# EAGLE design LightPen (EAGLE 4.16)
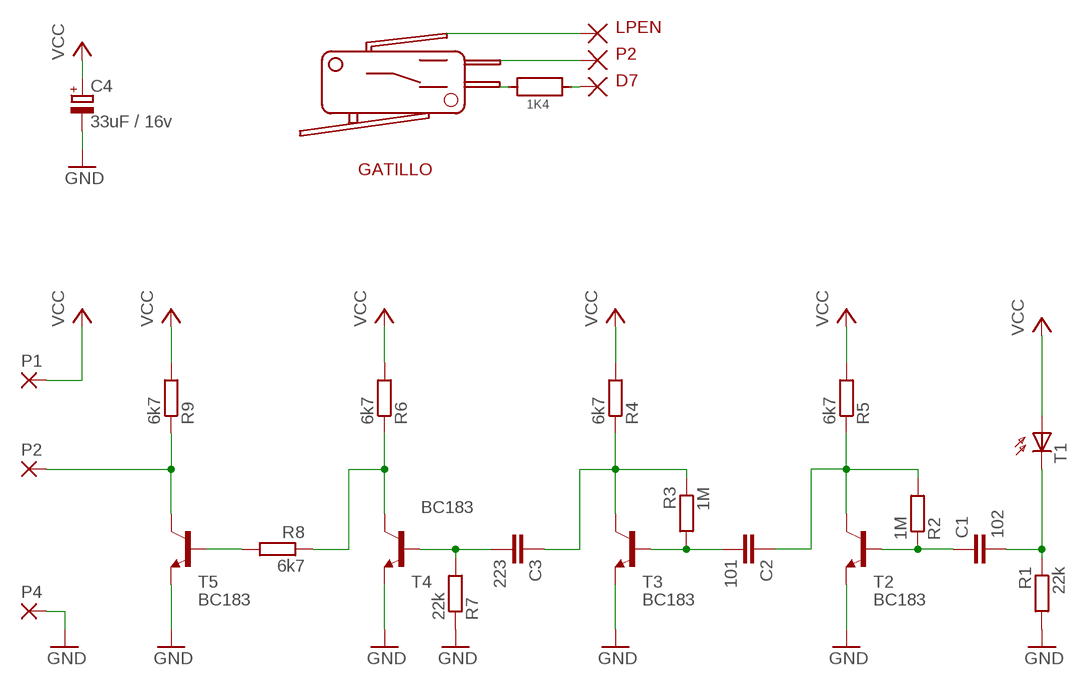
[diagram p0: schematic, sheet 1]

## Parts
C1  102  C-EU025-025X050  [C025-025X050]
C2  101  C-EU050-025X075  [C050-025X075]
C3  223  C-EU050-025X075  [C050-025X075]
C4  33uF / 16v  CPOL-EUE2.5-6  [E2,5-6]
P1  SMD2  [SMD1,27-2,54]
P2  SMD2  [SMD1,27-2,54]
P4  SMD2  [SMD1,27-2,54]
R1  22k  R-EU_0207/10  [0207/10]
R2  1M  R-EU_0207/10  [0207/10]
R3  1M  R-EU_0207/10  [0207/10]
R4  6k7  R-EU_0207/10  [0207/10]
R5  6k7  R-EU_0207/10  [0207/10]
R6  6k7  R-EU_0207/10  [0207/10]
R7  22k  R-EU_0207/10  [0207/10]
R8  6k7  R-EU_0207/10  [0207/10]
R9  6k7  R-EU_0207/10  [0207/10]
T1  SFH206  [SFH206]
T2  BC183  -NPN-TO92  [TO92]
T3  BC183  -NPN-TO92  [TO92]
T4  BC183  -NPN-TO92  [TO92]
T5  BC183  -NPN-TO92  [TO92]

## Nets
GND: C4.- P4.1(P) R1.2 R7.1 T2.1(E) T3.1(E) T4.1(E) T5.1(E)
N$1: P2.1(P) R9.1 T5.3(C)
N$2: R8.2 T5.2(B)
N$3: C1.2 R1.1 T1.K(C)
N$4: C1.1 R2.1 T2.2(B)
N$5: C2.1 R2.2 R5.1 T2.3(C)
N$6: C2.2 R3.2 T3.2(B)
N$7: C3.1 R3.1 R4.1 T3.3(C)
N$8: C3.2 R7.2 T4.2(B)
N$9: R6.1 R8.1 T4.3(C)
VCC: C4.+ P1.1(P) R4.2 R5.2 R6.2 R9.2 T1.A

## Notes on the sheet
- LPEN
- P2
- D7
- 1K4
- GATILLO

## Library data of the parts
C1-C3 = rcl:C-EU: CAPACITOR, European symbol
C4 = rcl:CPOL-EU: POLARIZED CAPACITOR, European symbol
P1 P2 P4 = wirepad:SMD2: SMD PAD
R1-R9 = rcl:R-EU_: RESISTOR, European symbol
T1 = opto-trans-siemens:SFH206: PHOTO DIODE
T2-T5 = transistor:*-NPN-: NPN Transistror

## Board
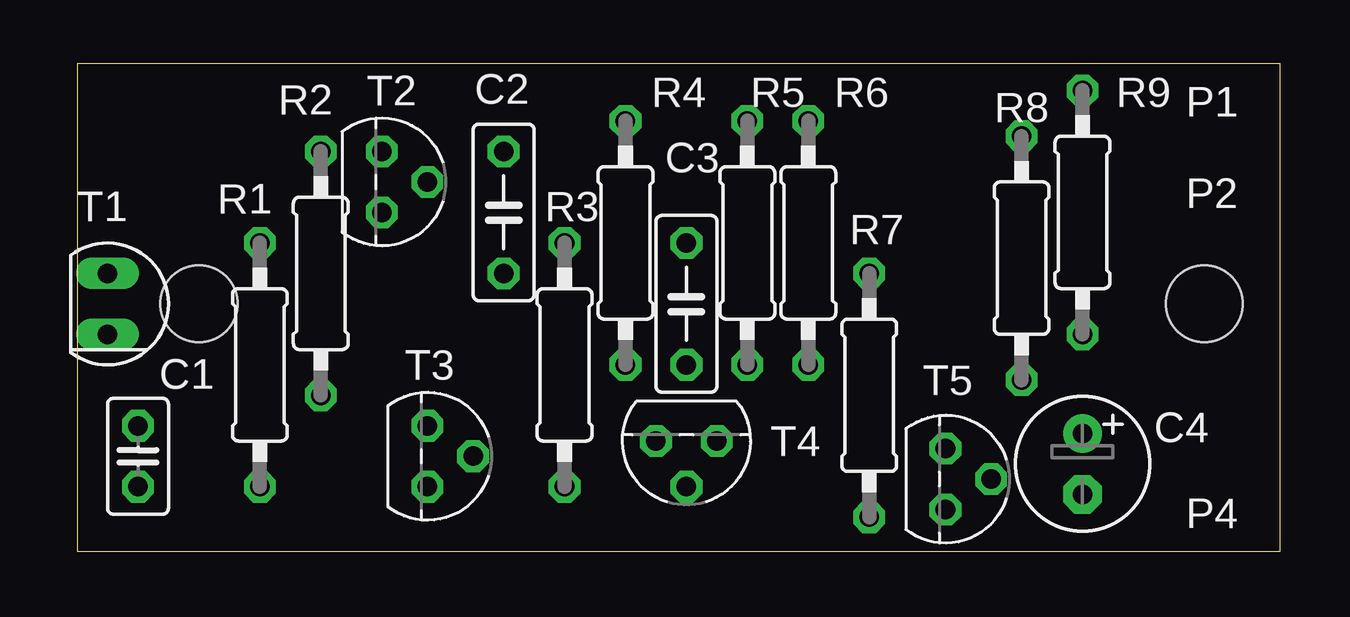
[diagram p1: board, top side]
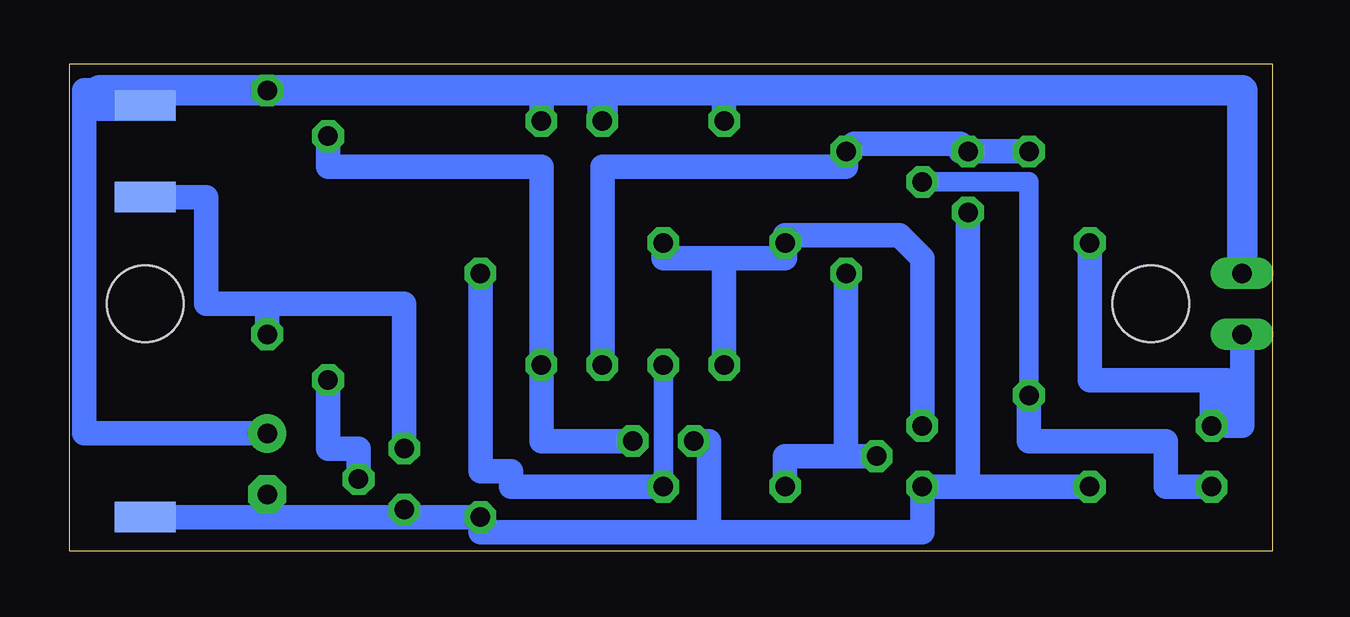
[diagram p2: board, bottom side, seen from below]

Size 50.14 x 20.31 mm. Coordinates in mm from the lower left corner, seen from the top.
Outline: 0,0 50.14,0 50.14,20.31 0,20.31 0,0
Copper layers (1*16): Top 0.035mm / dielectric 1.5mm / Bottom 0.035mm
Design rules "default": minimum track width 10mil, minimum drill 24mil, track to track 8mil, track to pad 8mil, pad to pad 8mil, via to via 8mil, smd to smd 8mil, copper to edge 40mil, drill to drill 8mil, minimum pad ring 10mil, minimum via ring 8mil, stop-mask expansion 4mil, vias tented up to drill 0mil, thermal gap 10mil
Holes 3.2 mm at 5.08,10.31 46.98,10.31

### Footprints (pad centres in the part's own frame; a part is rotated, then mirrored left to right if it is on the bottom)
C025-025X050 = drill 0.813 octagon: 1 -1.27,0; 2 1.27,0
C050-025X075 = drill 0.813 octagon: 1 -2.54,0; 2 2.54,0
E2,5-6 = drill 0.813 pad 1.6 round: + -1.27,0 | drill 0.813 pad 1.6 octagon: - 1.27,0
SMD1,27-2,54 = smd 1.27 x 2.54: 1 0,0
0207/10 = drill 0.813 octagon: 1 -5.08,0; 2 5.08,0
SFH206 = drill 0.813 long: A 0,-1.27; K 0,1.27
TO92 = drill 0.813 octagon: 1 1.27,0; 2 0,1.905; 3 -1.27,0

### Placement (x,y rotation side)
C1  2.54,3.96 90 top
C2  17.78,14.12 270 top
C3  25.39,10.31 270 top
C4  41.9,3.65 270 top
P1  46.98,18.57 270 bottom
P2  46.98,14.76 270 bottom
P4  46.98,1.42 270 bottom
R1  7.62,7.77 270 top
R2  10.15,11.58 90 top
R3  20.32,7.77 270 top
R4  22.86,12.85 90 top
R5  27.94,12.85 90 top
R6  30.48,12.85 90 top
R7  33.02,6.5 90 top
R8  39.36,12.22 270 top
R9  41.9,14.12 90 top
T1  1.27,10.31 180 top
T2  12.69,15.39 270 top
T3  14.6,3.96 270 top
T4  25.39,4.6 180 top
T5  36.19,3.01 270 top

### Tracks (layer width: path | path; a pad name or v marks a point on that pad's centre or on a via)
GND
  Bottom 1.016: 12.69,2.69 T2.1 | R1.2 12.69,2.69 | 12.69,2.69 T3.1 14.6,0.79 23.49,0.79 | 23.49,0.79 33.02,0.79 R7.1 36.19,1.42 | 41.9,1.42 P4.1 | 41.9,1.42 C4.- | 36.19,1.42 T5.1 | 36.19,1.42 41.9,1.42 | T4.1 23.49,4.6 23.49,0.79
N$1
  Bottom 1.016: P2.1 44.45,14.76 44.45,10.31 41.9,10.31 | R9.1 41.9,10.31 | 41.9,10.31 36.19,10.31 T5.3
N$2
  Bottom 1.016: T5.2 38.09,4.28 39.36,4.28 R8.2
N$3
  Bottom 1.016: R1.1 7.62,7.14 2.54,7.14 | 2.54,7.14 C1.2 | 2.54,7.14 1.9,7.14 1.9,5.23 1.27,5.23 T1.K
N$4
  Bottom 0.813: T2.2 10.15,15.39 R2.1
  Bottom 1.016: C1.1 4.44,2.69 4.44,4.6 10.15,4.6 R2.1
N$5
  Bottom 1.016: R2.2 T2.3 13.01,16.66 13.01,16.98 17.46,16.98 C2.1 17.78,16.03 27.94,16.03 R5.1
N$6
  Bottom 1.016: T3.2 17.78,3.96 | 17.78,3.96 20.32,3.96 R3.2 | 17.78,3.96 C2.2
N$7
  Bottom 1.016: T3.3 14.6,12.22 15.55,13.17 20.32,13.17 R3.1 20.32,12.22 22.86,12.22 | C3.1 25.39,12.22 22.86,12.22 | 22.86,12.22 R4.1
N$8
  Bottom 0.813: T4.2 C3.2
  Bottom 1.016: R7.2 33.02,3.33 31.75,3.33 31.75,2.69 T4.2
N$9
  Bottom 1.016: T4.3 30.48,4.6 R6.1 30.48,16.03 39.36,16.03 R8.1
VCC
  Bottom 1.016: 30.48,19.2 R6.2 | C4.+ 49.52,4.92 49.52,19.2 48.89,19.2 | 22.86,19.2 R4.2
  Bottom 1.27: T1.A 1.27,19.2 22.86,19.2 27.94,19.2 | 27.94,19.2 30.48,19.2 R9.2 48.89,19.2 48.89,18.57 P1.1 | 27.94,19.2 R5.2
